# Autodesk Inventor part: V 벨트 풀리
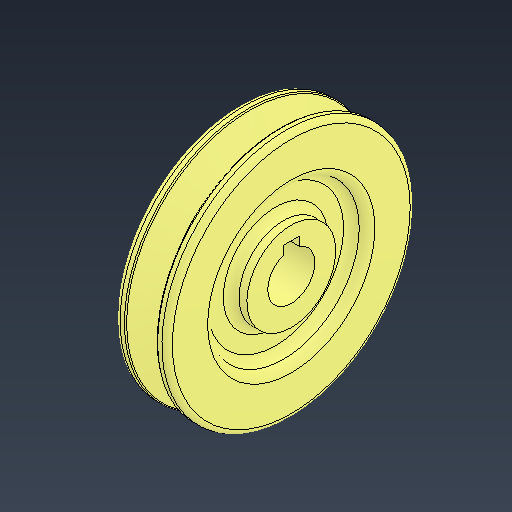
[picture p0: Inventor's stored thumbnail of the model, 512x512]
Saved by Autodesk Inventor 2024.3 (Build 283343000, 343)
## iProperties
Created: 2025-07
Part Number: V 벨트 풀리
Material: 강철, 주조
Document SubType Name: Modeling
Designer: user
Density: 7.85 g/cm^3
Appearance: 기본값
Author: jhkim
Sending System: Autodesk Inventor 2026
Preprocessor: ST-DEVELOPER v20.1
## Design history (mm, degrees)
feature "솔리드1"
node "솔리드2"
